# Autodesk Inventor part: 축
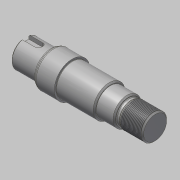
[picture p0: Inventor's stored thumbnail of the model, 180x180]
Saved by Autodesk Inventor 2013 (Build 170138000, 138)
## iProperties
Created: 2019-05
Part Number: 축
Material: 강철, 연강
Document SubType Name: Modeling
Designer: mduedu
Density: 1 g/cm^3
d0: 102.000 mm
d2: 21.000 mm
d3: 14.000 mm
d4: 30.000 mm
d5: 17.000 mm
d6: 22.000 mm
d7: 28.000 mm
d8: 25.000 mm
d9: 22.000 mm
d10: 20.000 mm
d12: 2.340 mm
d14: 30.00 deg
d15: 2.000 mm
d16: 1.000 mm
d17: 0.300 mm
d18: 1.000 mm
d21: 18.400 mm
d23: 2.340 mm
d24: 30.00 deg
d26: 0.600 mm
d27: 1.000 mm
d32: 1.000 mm
d35: 14.000 mm
d37: 6.000 mm
d38: 3.500 mm
d39: 0.00 deg
d40: 1.000 mm
Author: mduedu
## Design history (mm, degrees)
sketch "스케치1"
  geometry: L1 (0, 0)-(20, 0); L2 (20, 0)-(20, 11); L3 (20, 11)-(0, 11); L4 (0, 11)-(0, 0); L5 (20, 0)-(37, 0); L6 (37, 0)-(37, 14); L7 (37, 14)-(20, 14); L8 (20, 14)-(20, 0); L9 (37, 0)-(67, 0); L10 (67, 0)-(67, 12.5); L11 (67, 12.5)-(37, 12.5); L12 (37, 12.5)-(37, 0); L13 (67, 0)-(81, 0); L14 (81, 0)-(81, 11); L15 (81, 11)-(67, 11); L16 (67, 11)-(67, 0); L17 (81, 0)-(102, 0); L18 (102, 0)-(102, 10); L19 (102, 10)-(81, 10); L20 (81, 10)-(81, 0)
  constraints: 40 end point, 10 parallel, 5 horizontal, 5 perpendicular
  dimensions: "d0" = 102 distance between parallel lines of L18 L4; "d2" = 21 distance of L18.end L19.end; "d3" = 14 distance of L14.end L15.end; "d4" = 30 distance of L10.end L11.end; "d5" = 17 distance of L6.end L7.end; "d6" = 22 diameter of L3 L1; "d7" = 28 diameter of L7 L5; "d8" = 25 diameter of L11 L9; "d9" = 22 diameter of L15 L13; "d10" = 20 diameter of L19 L17
revolve "회전1" sketch "스케치1" stored, may be unused: angle "d11" = 90 deg
chamfer "모따기1" distance "d12" = 2.34; stored, may be unused: second distance "d13" = 2, angle "d14" = 30 deg
fillet "모깎기1" dims "d15" = 2, "d16" = 1
fillet "모깎기2" dims "d17" = 0.3
chamfer "모따기2" distance "d18" = 1; stored, may be unused: second distance "d19" = 2, angle "d20" = 30 deg
sketch "스케치2"
  geometry: L1 (102, -10)-(81, -10) reference; L2 (81, -10)-(81, -11) reference; L3 (81, -11)-(67, -11) reference; L4 (67, -11)-(67, -11.5) reference; L5 (67, -11.5)-(66, -12.5) reference; L6 (66, -12.5)-(37.3, -12.5) reference; L7 (37, -12.8)-(37, -14) reference; L8 (37, -14)-(22.876, -14) reference; L9 (21.876, -13.732)-(20.5, -12.938) reference; L10 (20, -12.072)-(20, -11) reference; L11 (20, -11)-(0, -11) reference; L12 (0, -11)-(0, 11) reference; L13 (0, 11)-(20, 11) reference; L14 (20, 11)-(20, 12.072) reference; L15 (20.5, 12.938)-(21.876, 13.732) reference; L16 (22.876, 14)-(37, 14) reference; L17 (37, 14)-(37, 12.8) reference; L18 (37.3, 12.5)-(66, 12.5) reference; L19 (66, 12.5)-(67, 11.5) reference; L20 (67, 11.5)-(67, 11) reference; L21 (67, 11)-(81, 11) reference; L22 (81, 11)-(81, 10) reference; L23 (81, 10)-(102, 10) reference; L24 (102, 10)-(102, -10) reference; L25 (0, 0)-(102, 0); L26 (81, 10)-(84.726, 10); L27 (83.34, 9.2)-(81, 9.2); L28 (81, 9.2)-(81, 10); L29 (84.726, 10)-(83.34, 9.2); A1 r 0.3 centre (37.3, -12.8) between (37.3, -12.5) and (37, -12.8) reference; A2 r 2 centre (22.876, -12) between (21.876, -13.732) and (22.876, -14) reference; A3 r 1 centre (21, -12.072) between (20, -12.072) and (20.5, -12.938) reference; A4 r 1 centre (21, 12.072) between (20.5, 12.938) and (20, 12.072) reference; A5 r 2 centre (22.876, 12) between (22.876, 14) and (21.876, 13.732) reference; A6 r 0.3 centre (37.3, 12.8) between (37, 12.8) and (37.3, 12.5) reference
  constraints: 10 end point, 1 horizontal, 1 midpoint, 1 parallel, 1 vertical
  dimensions: "d21" = 18.4 diameter of L27 L25; "d23" = 2.34 distance of L27.start L27.end; "d24" = 30 deg angle of L23 L29
revolve "회전2" sketch "스케치2" stored, may be unused: angle "d25" = 90 deg
fillet "모깎기3" dims "d26" = 0.6
chamfer "모따기3" distance "d27" = 1; stored, may be unused: second distance "d28" = 2, angle "d29" = 30 deg
feature "스레드1" dims "d30" = 10, "d31" = 0
chamfer "모따기4" distance "d32" = 1; stored, may be unused: second distance "d33" = 2, angle "d34" = 30 deg
node "작업 평면1"
sketch "스케치3"
  geometry: L1 (10, -3)-(-1, -3); L2 (-1, -3)-(-1, 3); L3 (-1, 3)-(10, 3); L4 (10, 3)-(10, -3); 3 further points
  constraints: 8 end point, 2 midpoint, 2 parallel, 1 coincident, 1 horizontal, 1 perpendicular, 1 vertical alignment, 2 other
  dimensions: "d35" = 14 dimension on L4; "d37" = 6 distance between parallel lines of L3 L1
extrude "돌출1" cut sketch "스케치3" distance "d38" = 3.5; taper "d39" = 0 deg
chamfer "모따기5" distance "d40" = 1; stored, may be unused: second distance "d41" = 2, angle "d42" = 30 deg
node "솔리드1"
node "절단 모서리 투영1"
